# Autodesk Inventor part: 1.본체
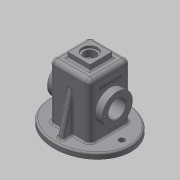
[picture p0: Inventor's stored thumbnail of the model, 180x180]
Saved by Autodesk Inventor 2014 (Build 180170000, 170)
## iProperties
Created: 2017-07
Part Number: 1.본체
Material: 일반
Document SubType Name: Modeling
Designer: 702-09
Density: 1 g/cm^3
Appearance: 기본값
Author: 702-09
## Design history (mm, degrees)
sketch "스케치1"
  geometry: 1 further point
sketch "스케치2" dims "d3" = 65, "d4" = 75
  geometry: 2 further points; 1 other entity
  constraints: 1 coincident, 2 other
extrude "돌출1" new body sketch "스케치2" distance "d1" = 10; taper "d2" = 0 deg
sketch "스케치3"
  geometry: L1 (37, -37)-(-37, -37); L2 (-37, -37)-(-37, 37); L3 (-37, 37)-(37, 37); L4 (37, 37)-(37, -37); L5 (37, -37)-(-37, 37); L6 (-37, -37)-(37, 37); 1 further point; 1 other entity
  constraints: 12 end point, 2 midpoint, 2 parallel, 1 horizontal, 1 perpendicular, 1 other
  dimensions: "d5" = 74 distance of L2.end L3.end; "d6" = 74 distance between parallel lines of L1 L3
extrude "돌출2" join sketch "스케치3" distance "d7" = 100; taper "d8" = 0 deg
sketch "스케치4"
  geometry: C1 r 5 at (-58, 0); C2 r 5 at (58, 0); 1 further point; 1 other entity
  constraints: 2 centre point, 1 other
  dimensions: "d9" = 58 distance of point (0, 0) C1.centre; "d10" = 58 distance of C2.centre point (0, 0); "d11" = 10 diameter of C2; "d12" = 10 diameter of C1
extrude "돌출3" cut sketch "스케치4" stored distance "d13" = 100; taper "d14" = 0 deg
sketch "스케치5"
  geometry: L1 (0, 0)-(-100, 0) reference; L2 (18.303, 37)-(-151.464, 37); C1 r 27.5 at (-45, 37); 1 further point
  constraints: 2 end point, 1 centre point, 1 parallel, 1 point on line
  dimensions: "d15" = 55 diameter of C1; "d16" = 55 distance of point (10, 37) C1.centre
extrude "돌출4" join sketch "스케치5" distance "d17" = 13; taper "d18" = 0 deg
sketch "스케치6"
  geometry: L1 (20, -20)-(-20, -20); L2 (-20, -20)-(-20, 20); L3 (-20, 20)-(20, 20); L4 (20, 20)-(20, -20); L5 (20, -20)-(-20, 20); L6 (-20, -20)-(20, 20); 1 further point
  constraints: 12 end point, 2 midpoint, 2 parallel, 1 horizontal, 1 perpendicular
  dimensions: "d19" = 40 distance of L2.end L3.end; "d20" = 40 distance of L1.end L2.end
extrude "돌출5" join sketch "스케치6" distance "d21" = 10; taper "d22" = 0 deg
sketch "스케치8"
  geometry: L1 (0, 0)-(-32, 0); L2 (-32, 105)-(0, 105); L3 (0, 105)-(0, 0); L4 (37, 110)-(37, 10) reference; L5 (37, 10)-(53, 10) reference; L6 (53, 10)-(53, 0) reference; L7 (53, 0)-(-53, 0) reference; L8 (-53, 0)-(-53, 10) reference; L9 (-53, 10)-(-37, 10) reference; L10 (-37, 10)-(-37, 27.5) reference; L11 (-37, 27.5)-(-50, 27.5) reference; L12 (-50, 27.5)-(-50, 82.5) reference; L13 (-50, 82.5)-(-37, 82.5) reference; L14 (-37, 82.5)-(-37, 110) reference; L15 (-37, 110)-(-20, 110) reference; L16 (-20, 110)-(-20, 120) reference; L17 (-20, 120)-(20, 120) reference; L18 (20, 120)-(20, 110) reference; L19 (20, 110)-(37, 110) reference; L20 (-75, 0)-(-75, 10) reference; L21 (-75, 10)-(-63, 10) reference; L22 (-63, 10)-(-63, 0) reference; L23 (-63, 0)-(-75, 0) reference; L24 (75, 10)-(75, 0) reference; L25 (75, 0)-(63, 0) reference; L26 (63, 0)-(63, 10) reference; L27 (63, 10)-(75, 10) reference; L28 (-25, 34.707)-(-25, 75.293); L29 (-25.146, 75.646)-(-31.854, 82.354); L30 (-32, 82.707)-(-32, 105); L31 (-31.854, 27.646)-(-25.146, 34.354); L32 (-32, 0)-(-32, 27.293); L33 (32, 105)-(0, 105); L34 (32, 82.707)-(32, 105); L35 (25.146, 75.646)-(31.854, 82.354); L36 (25, 34.707)-(25, 75.293); L37 (31.854, 27.646)-(25.146, 34.354); L38 (32, 0)-(32, 27.293); L39 (0, 0)-(32, 0); A1 r 0.5 centre (25.5, 75.293) between (25.146, 75.646) and (25, 75.293); A2 r 0.5 centre (31.5, 82.707) between (31.854, 82.354) and (32, 82.707); A3 r 0.5 centre (25.5, 34.707) between (25, 34.707) and (25.146, 34.354); A4 r 0.5 centre (31.5, 27.293) between (32, 27.293) and (31.854, 27.646); A5 r 0.5 centre (-31.5, 27.293) between (-31.854, 27.646) and (-32, 27.293); A6 r 0.5 centre (-25.5, 34.707) between (-25.146, 34.354) and (-25, 34.707); A7 r 0.5 centre (-25.5, 75.293) between (-25, 75.293) and (-25.146, 75.646); A8 r 0.5 centre (-31.5, 82.707) between (-32, 82.707) and (-31.854, 82.354); 8 further points
  constraints: 30 end point, 16 point on circle, 16 point on line, 16 tangent, 8 centre point, 7 equal radius, 6 symmetric about line, 2 parallel, 1 horizontal, 1 perpendicular
  dimensions: "d23" = 32 distance of L1.start L1.end; "d24" = 135 deg angle of L30 L29; "d26" = 135 deg angle of L32 L31; "d27" = 7 distance from line of point (-25, 34.5) L32; "d28" = 7 distance from line of point (-25, 75.5) L30; "d29" = 5 distance between parallel lines of L2 L15; "d70" = 0.5 radius of A1
extrude "돌출6" cut sketch "스케치8" stored distance "d30" = 64; taper "d31" = 0 deg
sketch "스케치9" dims "d32" = 45
  geometry: C1 r 27.5 at (0, 0) reference; 3 further points
  constraints: 1 coincident, 1 horizontal alignment, 2 other
hole "구멍1" sketch "스케치9" at (-22.5, 0) diameter "d33" = 3.242; stored, may be unused: countersink angle "d37" = 90 deg, drill point angle "d39" = 118 deg; dims "d34" = 8, "d35" = 4, "d36" = 2, "d38" = 10
hole "구멍2" diameter "d45" = 32; stored, may be unused: countersink angle "d49" = 90 deg, drill point angle "d51" = 0 deg; dims "d43" = 10, "d44" = 10, "d46" = 45, "d47" = 4, "d48" = 2, "d50" = 10
sketch "스케치10"
  geometry: 2 further points
  constraints: 1 coincident
hole "구멍3" sketch "스케치10" at (0, 0) diameter "d52" = 21; stored, may be unused: countersink angle "d56" = 90 deg, drill point angle "d58" = 0 deg; dims "d53" = 45, "d54" = 28, "d55" = 4, "d57" = 10
sketch "스케치11"
  geometry: L1 (65, 10)-(65, 0) reference; L2 (65, 0)-(32, 0) reference; L3 (32, 0)-(32, 105) reference; L4 (32, 105)-(10.5, 105) reference; L5 (10.5, 105)-(10.5, 116) reference; L6 (10.5, 116)-(14, 116) reference; L7 (14, 116)-(14, 120) reference; L8 (14, 120)-(20, 120) reference; L9 (20, 120)-(20, 110) reference; L10 (20, 110)-(37, 110) reference; L11 (37, 110)-(37, 10) reference; L12 (37, 10)-(65, 10) reference; L13 (-65, 0)-(-65, 10) reference; L14 (-65, 10)-(-37, 10) reference; L15 (-37, 10)-(-37, 110) reference; L16 (-37, 110)-(-20, 110) reference; L17 (-20, 110)-(-20, 120) reference; L18 (-20, 120)-(-14, 120) reference; L19 (-14, 120)-(-14, 116) reference; L20 (-14, 116)-(-10.5, 116) reference; L21 (-10.5, 116)-(-10.5, 105) reference; L22 (-10.5, 105)-(-32, 105) reference; L23 (-32, 105)-(-32, 0) reference; L24 (-32, 0)-(-65, 0) reference; L25 (55, 10)-(37, 82.194); 1 further point
  constraints: 2 end point, 2 point on line
  dimensions: "d59" = 10 distance from line of L1 L25.start; "d60" = 14 deg angle of L25 L1
feature "리브1" sketch "스케치11" dims "d61" = 1, "d62" = 10, "d63" = 0, "d64" = 0, "d65" = 1, "d66" = 1
fillet "모깎기1" dims "d67" = 8
fillet "모깎기2" dims "d68" = 8
fillet "모깎기3" dims "d69" = 3
fillet "모깎기4" dims "d71" = 3
chamfer "모따기1" distance "d72" = 1; stored, may be unused: second distance "d73" = 2, angle "d74" = 45 deg
sketch "스케치12"
  geometry: L1 (89, 66)-(0, 66) reference; L2 (-18, 9)-(-18, 49) reference; 2 further points
  constraints: 1 other
  dimensions: "d75" = 37 distance from line of L1 point (12, 29); "d76" = 30 distance from line of point (12, 29) L2
feature "엠보싱1" sketch "스케치12" dims "d77" = 0.5, "d78" = 0
node "솔리드1"
pattern_circular "원형 패턴1" dims angle "d41" = 360 deg
mirror "대칭1"
mirror "대칭2"
node "절단 모서리 투영1"
node "절단 모서리 투영2"
